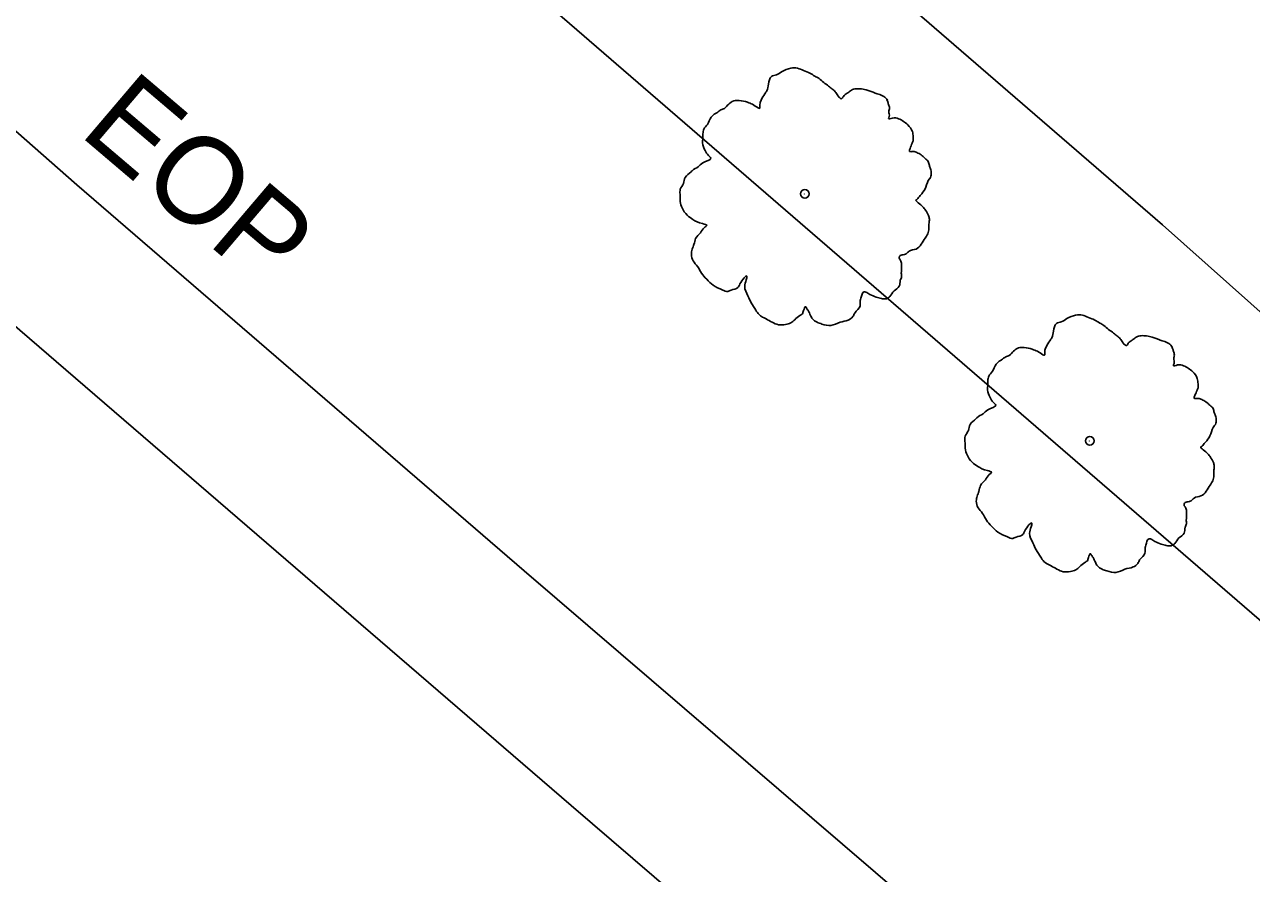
# Model space of a CAD drawing. Extents: x 2076109 to 2080761, y 592812 to 596750.
# Drawn here: x 2076830.5 to 2076900.8, y 596247.5 to 596296.2 of the extents above; entities that cross this region are included whole.
import ezdxf

# ---------------------------------------------------------------- set-up
doc = ezdxf.new("R2010")
doc.units = 0
for name, color, linetype in [('RD_EX_Fence_ChLk', 7, 'Continuous'), ('RD_EX_Misc', 7, 'Continuous'), ('RD_EX_Road', 7, 'Continuous'), ('RD_EX_Road_txCode', 7, 'Continuous'), ('RD_EX_VEG', 7, 'Continuous')]:
    doc.layers.add(name, color=color, linetype=linetype)

msp = doc.modelspace()

# ---------------------------------------------------------------- linework, layer by layer
at = {"layer": 'RD_EX_Fence_ChLk'}
msp.add_lwpolyline([(2076822.972, 596329.732), (2076907.019, 596257.073), (2076948.272, 596221.629), (2077023.379, 596156.571), (2077092.731, 596094.038)], dxfattribs=at)
msp.add_lwpolyline([(2076822.972, 596329.732), (2076907.019, 596257.073), (2076948.272, 596221.629), (2077023.379, 596156.571), (2077092.731, 596094.038)], dxfattribs=at)
at = {"layer": 'RD_EX_Misc'}
msp.add_lwpolyline([(2076810.466, 596295.642), (2076861.804, 596251.392), (2076900.569, 596218.064), (2076940.756, 596183.48), (2076983.389, 596147.001), (2077038.073, 596099.907), (2077086.972, 596057.778), (2077132.275, 596018.797), (2077181.847, 595976.05), (2077229.693, 595934.908), (2077274.19, 595896.66), (2077329.202, 595849.517), (2077358.599, 595824.219)], dxfattribs=at)
msp.add_lwpolyline([(2076810.466, 596295.642), (2076861.804, 596251.392), (2076900.569, 596218.064), (2076940.756, 596183.48), (2076983.389, 596147.001), (2077038.073, 596099.907), (2077086.972, 596057.778), (2077132.275, 596018.797), (2077181.847, 595976.05), (2077229.693, 595934.908), (2077274.19, 595896.66), (2077329.202, 595849.517), (2077358.599, 595824.219)], dxfattribs=at)
at = {"layer": 'RD_EX_Road'}
for points in [[(2077310.8, 596045.604), (2077284.614, 596043.933), (2077263.726, 596044.86), (2077236.773, 596048.361), (2077217.912, 596052.268), (2077187.348, 596060.961), (2077164.204, 596069.756), (2077147.202, 596077.801), (2077123.411, 596090.881), (2077107.361, 596101.022), (2077085.709, 596117.864), (2077071.396, 596130.863), (2077033.154, 596164.209), (2077005.119, 596187.538), (2076967.193, 596220.061), (2076925.043, 596258.574), (2076895.709, 596284.714), (2076870.355, 596306.64), (2076830.546, 596340.856)], [(2077310.8, 596045.604), (2077284.614, 596043.933), (2077263.726, 596044.86), (2077236.773, 596048.361), (2077217.912, 596052.268), (2077187.348, 596060.961), (2077164.204, 596069.756), (2077147.202, 596077.801), (2077123.411, 596090.881), (2077107.361, 596101.022), (2077085.709, 596117.864), (2077071.396, 596130.863), (2077033.154, 596164.209), (2077005.119, 596187.538), (2076967.193, 596220.061), (2076925.043, 596258.574), (2076895.709, 596284.714), (2076870.355, 596306.64), (2076830.546, 596340.856)], [(2077309.592, 595877.223), (2077282.743, 595900.374), (2077256.364, 595923.264), (2077227.255, 595948.475), (2077198.785, 595972.866), (2077175.799, 595992.64), (2077153.365, 596012.36), (2077130.636, 596031.731), (2077105.618, 596053.51), (2077080.494, 596075.056), (2077051.539, 596099.906), (2077024.399, 596123.257), (2077002.193, 596142.322), (2076978.911, 596162.671), (2076952.209, 596185.236), (2076929.194, 596204.759), (2076902.686, 596227.389), (2076879.244, 596247.551), (2076859.099, 596264.863), (2076833.455, 596286.99), (2076816.414, 596301.987)], [(2077309.592, 595877.223), (2077282.743, 595900.374), (2077256.364, 595923.264), (2077227.255, 595948.475), (2077198.785, 595972.866), (2077175.799, 595992.64), (2077153.365, 596012.36), (2077130.636, 596031.731), (2077105.618, 596053.51), (2077080.494, 596075.056), (2077051.539, 596099.906), (2077024.399, 596123.257), (2077002.193, 596142.322), (2076978.911, 596162.671), (2076952.209, 596185.236), (2076929.194, 596204.759), (2076902.686, 596227.389), (2076879.244, 596247.551), (2076859.099, 596264.863), (2076833.455, 596286.99), (2076816.414, 596301.987)]]:
    msp.add_lwpolyline(points, dxfattribs=at)
at = {"layer": 'RD_EX_VEG'}
for centre, radius in [((2076875.198, 596286.479), 0.25), ((2076875.198, 596286.479), 0.25), ((2076875.176, 596286.473), 0.0001), ((2076875.176, 596286.473), 0.0001), ((2076891.536, 596272.314), 0.25), ((2076891.536, 596272.314), 0.25), ((2076891.515, 596272.308), 0.0001), ((2076891.515, 596272.308), 0.0001)]:
    msp.add_circle(centre, radius, dxfattribs=at)
for points in [[(2076879.941, 596291.854), (2076879.728, 596292.067), (2076879.416, 596292.202), (2076879.161, 596292.287), (2076878.941, 596292.376), (2076878.705, 596292.446), (2076878.363, 596292.507), (2076878.062, 596292.5), (2076877.805, 596292.391), (2076877.622, 596292.252), (2076877.405, 596292.074), (2076877.292, 596291.941), (2076877.181, 596292.003), (2076877.083, 596292.119), (2076876.941, 596292.338), (2076876.751, 596292.5), (2076876.56, 596292.662), (2076876.277, 596292.87), (2076876.011, 596293.096), (2076875.769, 596293.236), (2076875.489, 596293.409), (2076875.123, 596293.556), (2076874.775, 596293.688), (2076874.385, 596293.691), (2076873.887, 596293.492), (2076873.565, 596293.306), (2076873.289, 596293.213), (2076873.112, 596292.773), (2076873.019, 596292.393), (2076872.908, 596292.225), (2076872.69, 596291.852), (2076872.621, 596291.616), (2076872.586, 596291.383), (2076872.513, 596291.413), (2076872.195, 596291.617), (2076871.902, 596291.735), (2076871.433, 596291.839), (2076871.115, 596291.814), (2076870.829, 596291.631), (2076870.583, 596291.38), (2076870.378, 596291.293), (2076870.142, 596291.132), (2076870.075, 596291.091), (2076869.826, 596290.876), (2076869.611, 596290.469), (2076869.404, 596290.186), (2076869.353, 596289.934), (2076869.354, 596289.703), (2076869.325, 596289.4), (2076869.484, 596288.969), (2076869.667, 596288.683), (2076869.803, 596288.534), (2076869.346, 596288.267), (2076869.081, 596288.032), (2076868.727, 596287.809), (2076868.679, 596287.752), (2076868.333, 596287.422), (2076868.237, 596287.078), (2076868.051, 596286.744), (2076868.039, 596286.459), (2076868.054, 596286.052), (2076868.156, 596285.671), (2076868.456, 596285.252), (2076868.776, 596285.012), (2076869.328, 596284.773), (2076869.567, 596284.668), (2076869.434, 596284.551), (2076869.21, 596284.249), (2076868.935, 596283.926), (2076868.839, 596283.581), (2076868.737, 596283.307), (2076868.689, 596283.019), (2076868.791, 596282.637), (2076869.047, 596282.321), (2076869.274, 596281.932), (2076869.568, 596281.583), (2076869.933, 596281.241), (2076870.487, 596280.966), (2076870.777, 596280.884), (2076870.966, 596280.952), (2076871.362, 596281.108), (2076871.469, 596281.312), (2076871.877, 596281.753), (2076871.839, 596281.555), (2076871.746, 596281.175), (2076871.933, 596280.623), (2076872.124, 596280.23), (2076872.388, 596279.809), (2076872.568, 596279.557), (2076872.979, 596279.307), (2076873.313, 596279.121), (2076873.679, 596278.974), (2076874.086, 596278.989), (2076874.397, 596279.085), (2076874.613, 596279.262), (2076874.913, 596279.499), (2076875.065, 596279.6)], [(2076879.941, 596291.854), (2076879.728, 596292.067), (2076879.416, 596292.202), (2076879.161, 596292.287), (2076878.941, 596292.376), (2076878.705, 596292.446), (2076878.363, 596292.507), (2076878.062, 596292.5), (2076877.805, 596292.391), (2076877.622, 596292.252), (2076877.405, 596292.074), (2076877.292, 596291.941), (2076877.181, 596292.003), (2076877.083, 596292.119), (2076876.941, 596292.338), (2076876.751, 596292.5), (2076876.56, 596292.662), (2076876.277, 596292.87), (2076876.011, 596293.096), (2076875.769, 596293.236), (2076875.489, 596293.409), (2076875.123, 596293.556), (2076874.775, 596293.688), (2076874.385, 596293.691), (2076873.887, 596293.492), (2076873.565, 596293.306), (2076873.289, 596293.213), (2076873.112, 596292.773), (2076873.019, 596292.393), (2076872.908, 596292.225), (2076872.69, 596291.852), (2076872.621, 596291.616), (2076872.586, 596291.383), (2076872.513, 596291.413), (2076872.195, 596291.617), (2076871.902, 596291.735), (2076871.433, 596291.839), (2076871.115, 596291.814), (2076870.829, 596291.631), (2076870.583, 596291.38), (2076870.378, 596291.293), (2076870.142, 596291.132), (2076870.075, 596291.091), (2076869.826, 596290.876), (2076869.611, 596290.469), (2076869.404, 596290.186), (2076869.353, 596289.934), (2076869.354, 596289.703), (2076869.325, 596289.4), (2076869.484, 596288.969), (2076869.667, 596288.683), (2076869.803, 596288.534), (2076869.346, 596288.267), (2076869.081, 596288.032), (2076868.727, 596287.809), (2076868.679, 596287.752), (2076868.333, 596287.422), (2076868.237, 596287.078), (2076868.051, 596286.744), (2076868.039, 596286.459), (2076868.054, 596286.052), (2076868.156, 596285.671), (2076868.456, 596285.252), (2076868.776, 596285.012), (2076869.328, 596284.773), (2076869.567, 596284.668), (2076869.434, 596284.551), (2076869.21, 596284.249), (2076868.935, 596283.926), (2076868.839, 596283.581), (2076868.737, 596283.307), (2076868.689, 596283.019), (2076868.791, 596282.637), (2076869.047, 596282.321), (2076869.274, 596281.932), (2076869.568, 596281.583), (2076869.933, 596281.241), (2076870.487, 596280.966), (2076870.777, 596280.884), (2076870.966, 596280.952), (2076871.362, 596281.108), (2076871.469, 596281.312), (2076871.877, 596281.753), (2076871.839, 596281.555), (2076871.746, 596281.175), (2076871.933, 596280.623), (2076872.124, 596280.23), (2076872.388, 596279.809), (2076872.568, 596279.557), (2076872.979, 596279.307), (2076873.313, 596279.121), (2076873.679, 596278.974), (2076874.086, 596278.989), (2076874.397, 596279.085), (2076874.613, 596279.262), (2076874.913, 596279.499), (2076875.065, 596279.6)], [(2076875.065, 596279.6), (2076875.121, 596279.782), (2076875.245, 596280.004), (2076875.286, 596279.937), (2076875.386, 596279.785), (2076875.515, 596279.512), (2076875.638, 596279.309), (2076875.901, 596279.118), (2076876.176, 596279.016), (2076876.696, 596278.934), (2076877.213, 596279.118), (2076877.682, 596279.244), (2076877.949, 596279.443), (2076878.057, 596279.647), (2076878.361, 596280.044), (2076878.371, 596280.364), (2076878.414, 596280.491), (2076878.597, 596280.861), (2076878.686, 596280.85), (2076878.928, 596280.71), (2076879.294, 596280.563), (2076879.585, 596280.48), (2076879.87, 596280.467), (2076880.072, 596280.59), (2076880.312, 596280.911), (2076880.609, 596281.183), (2076880.649, 596281.346), (2076880.67, 596281.525), (2076880.743, 596281.726), (2076880.726, 596281.937), (2076880.747, 596282.116), (2076880.735, 596282.257), (2076880.737, 596282.452), (2076880.685, 596282.661), (2076880.603, 596282.796), (2076880.662, 596282.942), (2076880.906, 596282.998), (2076881.008, 596283.041), (2076881.173, 596283.196), (2076881.571, 596283.317), (2076881.868, 596283.59), (2076882.105, 596283.946), (2076882.245, 596284.187), (2076882.309, 596284.494), (2076882.319, 596284.814), (2076882.337, 596285.028), (2076882.284, 596285.236), (2076882.118, 596285.542), (2076881.96, 596285.742), (2076881.693, 596285.969), (2076881.573, 596286.136), (2076881.625, 596286.158), (2076881.722, 596286.272), (2076881.9, 596286.482), (2076882.134, 596286.873), (2076882.344, 596287.351), (2076882.36, 596287.37), (2076882.446, 596287.625), (2076882.404, 596287.923), (2076882.335, 596288.112), (2076882.264, 596288.337), (2076882.09, 596288.518), (2076881.861, 596288.712), (2076881.62, 596288.852), (2076881.402, 596288.906), (2076881.188, 596288.924), (2076881.228, 596289.087), (2076881.346, 596289.38), (2076881.405, 596289.526), (2076881.405, 596289.757), (2076881.363, 596290.055), (2076881.101, 596290.441), (2076880.576, 596290.789), (2076880.218, 596290.831), (2076879.991, 596290.795), (2076880.034, 596290.922), (2076880.011, 596291.204), (2076880.048, 596291.402), (2076879.996, 596291.61), (2076879.946, 596291.784), (2076879.903, 596291.887)], [(2076875.065, 596279.6), (2076875.121, 596279.782), (2076875.245, 596280.004), (2076875.286, 596279.937), (2076875.386, 596279.785), (2076875.515, 596279.512), (2076875.638, 596279.309), (2076875.901, 596279.118), (2076876.176, 596279.016), (2076876.696, 596278.934), (2076877.213, 596279.118), (2076877.682, 596279.244), (2076877.949, 596279.443), (2076878.057, 596279.647), (2076878.361, 596280.044), (2076878.371, 596280.364), (2076878.414, 596280.491), (2076878.597, 596280.861), (2076878.686, 596280.85), (2076878.928, 596280.71), (2076879.294, 596280.563), (2076879.585, 596280.48), (2076879.87, 596280.467), (2076880.072, 596280.59), (2076880.312, 596280.911), (2076880.609, 596281.183), (2076880.649, 596281.346), (2076880.67, 596281.525), (2076880.743, 596281.726), (2076880.726, 596281.937), (2076880.747, 596282.116), (2076880.735, 596282.257), (2076880.737, 596282.452), (2076880.685, 596282.661), (2076880.603, 596282.796), (2076880.662, 596282.942), (2076880.906, 596282.998), (2076881.008, 596283.041), (2076881.173, 596283.196), (2076881.571, 596283.317), (2076881.868, 596283.59), (2076882.105, 596283.946), (2076882.245, 596284.187), (2076882.309, 596284.494), (2076882.319, 596284.814), (2076882.337, 596285.028), (2076882.284, 596285.236), (2076882.118, 596285.542), (2076881.96, 596285.742), (2076881.693, 596285.969), (2076881.573, 596286.136), (2076881.625, 596286.158), (2076881.722, 596286.272), (2076881.9, 596286.482), (2076882.134, 596286.873), (2076882.344, 596287.351), (2076882.36, 596287.37), (2076882.446, 596287.625), (2076882.404, 596287.923), (2076882.335, 596288.112), (2076882.264, 596288.337), (2076882.09, 596288.518), (2076881.861, 596288.712), (2076881.62, 596288.852), (2076881.402, 596288.906), (2076881.188, 596288.924), (2076881.228, 596289.087), (2076881.346, 596289.38), (2076881.405, 596289.526), (2076881.405, 596289.757), (2076881.363, 596290.055), (2076881.101, 596290.441), (2076880.576, 596290.789), (2076880.218, 596290.831), (2076879.991, 596290.795), (2076880.034, 596290.922), (2076880.011, 596291.204), (2076880.048, 596291.402), (2076879.996, 596291.61), (2076879.946, 596291.784), (2076879.903, 596291.887)], [(2076896.28, 596277.689), (2076896.067, 596277.902), (2076895.755, 596278.037), (2076895.5, 596278.122), (2076895.28, 596278.211), (2076895.044, 596278.28), (2076894.702, 596278.341), (2076894.401, 596278.335), (2076894.144, 596278.225), (2076893.96, 596278.086), (2076893.744, 596277.909), (2076893.631, 596277.776), (2076893.52, 596277.838), (2076893.422, 596277.954), (2076893.28, 596278.173), (2076893.089, 596278.335), (2076892.899, 596278.497), (2076892.616, 596278.704), (2076892.35, 596278.931), (2076892.108, 596279.071), (2076891.828, 596279.243), (2076891.462, 596279.391), (2076891.114, 596279.522), (2076890.724, 596279.526), (2076890.226, 596279.326), (2076889.904, 596279.141), (2076889.628, 596279.048), (2076889.451, 596278.608), (2076889.358, 596278.228), (2076889.247, 596278.059), (2076889.029, 596277.687), (2076888.96, 596277.451), (2076888.925, 596277.218), (2076888.852, 596277.247), (2076888.534, 596277.452), (2076888.241, 596277.57), (2076887.771, 596277.674), (2076887.454, 596277.648), (2076887.168, 596277.466), (2076886.922, 596277.215), (2076886.717, 596277.128), (2076886.481, 596276.967), (2076886.414, 596276.926), (2076886.165, 596276.711), (2076885.95, 596276.303), (2076885.743, 596276.021), (2076885.692, 596275.768), (2076885.693, 596275.538), (2076885.664, 596275.234), (2076885.823, 596274.804), (2076886.006, 596274.518), (2076886.142, 596274.369), (2076885.685, 596274.102), (2076885.42, 596273.867), (2076885.066, 596273.644), (2076885.018, 596273.587), (2076884.672, 596273.257), (2076884.576, 596272.913), (2076884.39, 596272.579), (2076884.378, 596272.294), (2076884.393, 596271.887), (2076884.495, 596271.506), (2076884.795, 596271.087), (2076885.115, 596270.847), (2076885.667, 596270.608), (2076885.905, 596270.503), (2076885.773, 596270.386), (2076885.549, 596270.084), (2076885.274, 596269.76), (2076885.178, 596269.416), (2076885.076, 596269.142), (2076885.028, 596268.854), (2076885.13, 596268.472), (2076885.386, 596268.156), (2076885.613, 596267.767), (2076885.907, 596267.418), (2076886.271, 596267.076), (2076886.826, 596266.801), (2076887.116, 596266.719), (2076887.305, 596266.787), (2076887.7, 596266.943), (2076887.808, 596267.147), (2076888.216, 596267.588), (2076888.178, 596267.39), (2076888.085, 596267.01), (2076888.272, 596266.458), (2076888.463, 596266.065), (2076888.727, 596265.643), (2076888.907, 596265.392), (2076889.318, 596265.142), (2076889.652, 596264.956), (2076890.018, 596264.808), (2076890.425, 596264.824), (2076890.736, 596264.92), (2076890.952, 596265.097), (2076891.252, 596265.334), (2076891.404, 596265.435)], [(2076896.28, 596277.689), (2076896.067, 596277.902), (2076895.755, 596278.037), (2076895.5, 596278.122), (2076895.28, 596278.211), (2076895.044, 596278.28), (2076894.702, 596278.341), (2076894.401, 596278.335), (2076894.144, 596278.225), (2076893.96, 596278.086), (2076893.744, 596277.909), (2076893.631, 596277.776), (2076893.52, 596277.838), (2076893.422, 596277.954), (2076893.28, 596278.173), (2076893.089, 596278.335), (2076892.899, 596278.497), (2076892.616, 596278.704), (2076892.35, 596278.931), (2076892.108, 596279.071), (2076891.828, 596279.243), (2076891.462, 596279.391), (2076891.114, 596279.522), (2076890.724, 596279.526), (2076890.226, 596279.326), (2076889.904, 596279.141), (2076889.628, 596279.048), (2076889.451, 596278.608), (2076889.358, 596278.228), (2076889.247, 596278.059), (2076889.029, 596277.687), (2076888.96, 596277.451), (2076888.925, 596277.218), (2076888.852, 596277.247), (2076888.534, 596277.452), (2076888.241, 596277.57), (2076887.771, 596277.674), (2076887.454, 596277.648), (2076887.168, 596277.466), (2076886.922, 596277.215), (2076886.717, 596277.128), (2076886.481, 596276.967), (2076886.414, 596276.926), (2076886.165, 596276.711), (2076885.95, 596276.303), (2076885.743, 596276.021), (2076885.692, 596275.768), (2076885.693, 596275.538), (2076885.664, 596275.234), (2076885.823, 596274.804), (2076886.006, 596274.518), (2076886.142, 596274.369), (2076885.685, 596274.102), (2076885.42, 596273.867), (2076885.066, 596273.644), (2076885.018, 596273.587), (2076884.672, 596273.257), (2076884.576, 596272.913), (2076884.39, 596272.579), (2076884.378, 596272.294), (2076884.393, 596271.887), (2076884.495, 596271.506), (2076884.795, 596271.087), (2076885.115, 596270.847), (2076885.667, 596270.608), (2076885.905, 596270.503), (2076885.773, 596270.386), (2076885.549, 596270.084), (2076885.274, 596269.76), (2076885.178, 596269.416), (2076885.076, 596269.142), (2076885.028, 596268.854), (2076885.13, 596268.472), (2076885.386, 596268.156), (2076885.613, 596267.767), (2076885.907, 596267.418), (2076886.271, 596267.076), (2076886.826, 596266.801), (2076887.116, 596266.719), (2076887.305, 596266.787), (2076887.7, 596266.943), (2076887.808, 596267.147), (2076888.216, 596267.588), (2076888.178, 596267.39), (2076888.085, 596267.01), (2076888.272, 596266.458), (2076888.463, 596266.065), (2076888.727, 596265.643), (2076888.907, 596265.392), (2076889.318, 596265.142), (2076889.652, 596264.956), (2076890.018, 596264.808), (2076890.425, 596264.824), (2076890.736, 596264.92), (2076890.952, 596265.097), (2076891.252, 596265.334), (2076891.404, 596265.435)], [(2076891.404, 596265.435), (2076891.46, 596265.616), (2076891.584, 596265.839), (2076891.624, 596265.772), (2076891.725, 596265.62), (2076891.854, 596265.347), (2076891.977, 596265.144), (2076892.24, 596264.953), (2076892.514, 596264.851), (2076893.035, 596264.769), (2076893.552, 596264.953), (2076894.021, 596265.079), (2076894.288, 596265.278), (2076894.396, 596265.482), (2076894.7, 596265.879), (2076894.71, 596266.199), (2076894.753, 596266.326), (2076894.936, 596266.695), (2076895.025, 596266.685), (2076895.267, 596266.545), (2076895.633, 596266.397), (2076895.924, 596266.315), (2076896.209, 596266.302), (2076896.411, 596266.425), (2076896.651, 596266.746), (2076896.948, 596267.018), (2076896.988, 596267.181), (2076897.009, 596267.36), (2076897.082, 596267.561), (2076897.064, 596267.772), (2076897.086, 596267.951), (2076897.074, 596268.092), (2076897.076, 596268.287), (2076897.024, 596268.495), (2076896.942, 596268.631), (2076897.001, 596268.777), (2076897.245, 596268.832), (2076897.347, 596268.876), (2076897.512, 596269.031), (2076897.91, 596269.152), (2076898.207, 596269.424), (2076898.444, 596269.78), (2076898.584, 596270.022), (2076898.648, 596270.329), (2076898.658, 596270.649), (2076898.676, 596270.863), (2076898.623, 596271.071), (2076898.457, 596271.377), (2076898.299, 596271.577), (2076898.032, 596271.804), (2076897.912, 596271.971), (2076897.964, 596271.993), (2076898.061, 596272.107), (2076898.239, 596272.317), (2076898.473, 596272.708), (2076898.683, 596273.186), (2076898.699, 596273.205), (2076898.785, 596273.46), (2076898.743, 596273.758), (2076898.674, 596273.947), (2076898.603, 596274.172), (2076898.429, 596274.353), (2076898.2, 596274.547), (2076897.958, 596274.687), (2076897.741, 596274.741), (2076897.527, 596274.759), (2076897.567, 596274.921), (2076897.685, 596275.215), (2076897.744, 596275.361), (2076897.743, 596275.592), (2076897.702, 596275.89), (2076897.44, 596276.276), (2076896.915, 596276.624), (2076896.557, 596276.666), (2076896.33, 596276.63), (2076896.373, 596276.757), (2076896.35, 596277.039), (2076896.387, 596277.237), (2076896.335, 596277.445), (2076896.285, 596277.619), (2076896.241, 596277.722)], [(2076891.404, 596265.435), (2076891.46, 596265.616), (2076891.584, 596265.839), (2076891.624, 596265.772), (2076891.725, 596265.62), (2076891.854, 596265.347), (2076891.977, 596265.144), (2076892.24, 596264.953), (2076892.514, 596264.851), (2076893.035, 596264.769), (2076893.552, 596264.953), (2076894.021, 596265.079), (2076894.288, 596265.278), (2076894.396, 596265.482), (2076894.7, 596265.879), (2076894.71, 596266.199), (2076894.753, 596266.326), (2076894.936, 596266.695), (2076895.025, 596266.685), (2076895.267, 596266.545), (2076895.633, 596266.397), (2076895.924, 596266.315), (2076896.209, 596266.302), (2076896.411, 596266.425), (2076896.651, 596266.746), (2076896.948, 596267.018), (2076896.988, 596267.181), (2076897.009, 596267.36), (2076897.082, 596267.561), (2076897.064, 596267.772), (2076897.086, 596267.951), (2076897.074, 596268.092), (2076897.076, 596268.287), (2076897.024, 596268.495), (2076896.942, 596268.631), (2076897.001, 596268.777), (2076897.245, 596268.832), (2076897.347, 596268.876), (2076897.512, 596269.031), (2076897.91, 596269.152), (2076898.207, 596269.424), (2076898.444, 596269.78), (2076898.584, 596270.022), (2076898.648, 596270.329), (2076898.658, 596270.649), (2076898.676, 596270.863), (2076898.623, 596271.071), (2076898.457, 596271.377), (2076898.299, 596271.577), (2076898.032, 596271.804), (2076897.912, 596271.971), (2076897.964, 596271.993), (2076898.061, 596272.107), (2076898.239, 596272.317), (2076898.473, 596272.708), (2076898.683, 596273.186), (2076898.699, 596273.205), (2076898.785, 596273.46), (2076898.743, 596273.758), (2076898.674, 596273.947), (2076898.603, 596274.172), (2076898.429, 596274.353), (2076898.2, 596274.547), (2076897.958, 596274.687), (2076897.741, 596274.741), (2076897.527, 596274.759), (2076897.567, 596274.921), (2076897.685, 596275.215), (2076897.744, 596275.361), (2076897.743, 596275.592), (2076897.702, 596275.89), (2076897.44, 596276.276), (2076896.915, 596276.624), (2076896.557, 596276.666), (2076896.33, 596276.63), (2076896.373, 596276.757), (2076896.35, 596277.039), (2076896.387, 596277.237), (2076896.335, 596277.445), (2076896.285, 596277.619), (2076896.241, 596277.722)]]:
    msp.add_spline(points, degree=3, dxfattribs=at)

# ---------------------------------------------------------------- texts
at = {"layer": 'RD_EX_Road_txCode'}
msp.add_text('EOP', height=5, rotation=319.62738, dxfattribs=at).set_placement((2076833.5, 596289.918))
msp.add_text('EOP', height=5, rotation=319.62738, dxfattribs=at).set_placement((2076833.5, 596289.918))

doc.saveas('drawing.dxf')
